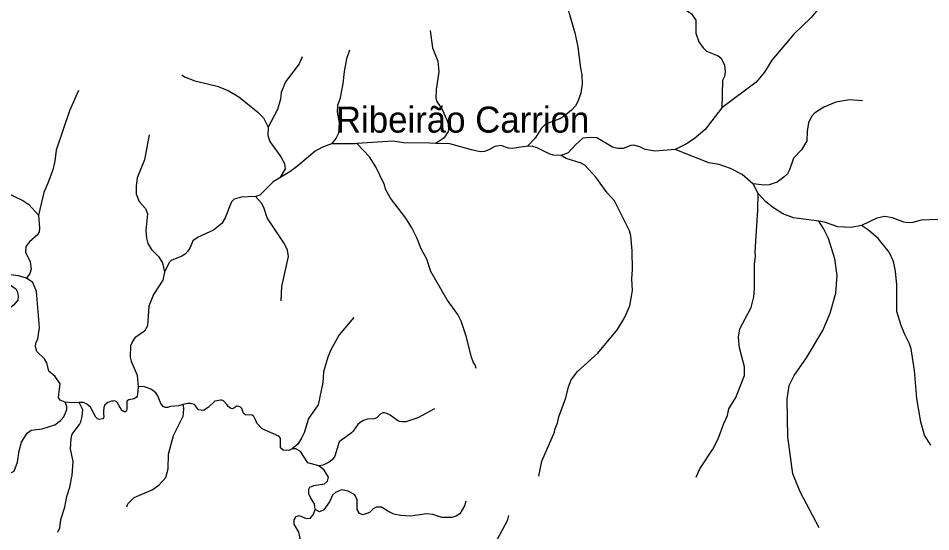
# Model space of a CAD drawing. Extents: x 500 to 555.2, y 9115.7 to 9171.
# Drawn here: x 511.43 to 518.44, y 9126.41 to 9130.35 of the extents above; entities that cross this region are included whole.
import ezdxf
from ezdxf.enums import TextEntityAlignment as Align

# ---------------------------------------------------------------- set-up
doc = ezdxf.new("R2010")
doc.units = 0
doc.header["$LTSCALE"] = 0.064
doc.layers.add('61', color=7, linetype='Continuous')
doc.layers.add('7', color=7, linetype='Continuous', lineweight=25)

msp = doc.modelspace()

# ---------------------------------------------------------------- linework, layer by layer
at = {"layer": '7'}
msp.add_line((512.5491, 9128.3991), (512.5369, 9128.3375), dxfattribs=at)
for points in [[(515.2472, 9130.9806), (515.3445, 9130.9612), (515.3856, 9130.9335), (515.4135, 9130.9056), (515.4543, 9130.8482), (515.4565, 9130.8327), (515.6452, 9130.44), (515.704, 9130.2374), (515.7268, 9130.1297), (515.7435, 9129.9839), (515.7581, 9129.9117), (515.7596, 9129.845), (515.7492, 9129.774), (515.7249, 9129.7092), (515.7071, 9129.6771), (515.678, 9129.6431), (515.6218, 9129.5967), (515.5872, 9129.5777), (515.4771, 9129.5371), (515.446, 9129.5058), (515.3982, 9129.4273), (515.3402, 9129.3668)], [(516.2338, 9130.6735), (516.2441, 9130.6339), (516.27, 9130.5794), (516.2861, 9130.5676), (516.3069, 9130.5407), (516.4113, 9130.4831), (516.5432, 9130.4204), (516.5986, 9130.3831), (516.6337, 9130.3346), (516.634, 9130.2335), (516.6572, 9130.1671), (516.6887, 9130.1225), (516.7156, 9130.0973), (516.8053, 9130.0601), (516.8241, 9130.0444), (516.8523, 9129.992), (516.8587, 9129.9383), (516.8521, 9129.9008), (516.8391, 9129.8706), (516.8338, 9129.6601)], [(517.5727, 9130.4215), (517.5725, 9130.42), (517.5159, 9130.3525), (517.3872, 9130.227), (517.2162, 9130.0264), (517.1615, 9129.9357), (517.0964, 9129.8592), (516.8338, 9129.6601)], [(511.3289, 9130.3305), (511.3189, 9130.3063), (511.3144, 9130.2586), (511.3374, 9130.074), (511.3341, 9130.0052), (511.3244, 9129.9466), (511.2703, 9129.799), (511.2587, 9129.7486), (511.2586, 9129.7042), (511.2819, 9129.5853), (511.3334, 9129.4822), (511.3373, 9129.4323), (511.3133, 9129.3694), (511.2704, 9129.2126), (511.267, 9129.128), (511.2717, 9129.0806), (511.2884, 9129.048), (511.3216, 9129.0169), (511.462, 9128.9504), (511.5059, 9128.918), (511.5809, 9128.8379)], [(514.591, 9130.2543), (514.6093, 9130.1219), (514.6505, 9130.0188), (514.6588, 9129.9368), (514.6377, 9129.8017), (514.6346, 9129.735), (514.6415, 9129.7089), (514.6852, 9129.6424), (514.718, 9129.5753), (514.7293, 9129.5399), (514.7321, 9129.4855), (514.6995, 9129.4309), (514.634, 9129.3885)], [(513.6066, 9130.0527), (513.5842, 9129.9998), (513.48, 9129.8612), (513.4454, 9129.7793), (513.44, 9129.729), (513.4172, 9129.6475), (513.3472, 9129.5126)], [(513.971, 9130.1042), (513.9493, 9130.0374), (513.9306, 9129.9415), (513.9192, 9129.8449), (513.896, 9129.729), (513.8799, 9129.6797), (513.8766, 9129.6299), (513.8929, 9129.5459), (513.888, 9129.4678), (513.8659, 9129.4256), (513.8338, 9129.3853)], [(512.6822, 9129.9144), (512.7042, 9129.9006), (512.783, 9129.8693), (512.9547, 9129.8279), (513.0399, 9129.795), (513.12, 9129.7446), (513.2681, 9129.6277), (513.3096, 9129.5841), (513.3472, 9129.5126)], [(511.8899, 9129.7954), (511.8186, 9129.6389), (511.7163, 9129.3352), (511.7078, 9129.2517), (511.6917, 9129.185), (511.6538, 9129.0827), (511.6211, 9129.0121), (511.5809, 9128.8379)], [(517.9129, 9129.716), (517.8138, 9129.7229), (517.7101, 9129.7054), (517.6179, 9129.6663), (517.5462, 9129.6202), (517.5246, 9129.5966), (517.4985, 9129.5492), (517.4885, 9129.4808), (517.4851, 9129.4073), (517.4463, 9129.3393), (517.383, 9129.2744), (517.3538, 9129.185), (517.3366, 9129.1545), (517.3102, 9129.1282), (517.2577, 9129.0903), (517.1959, 9129.0693), (517.1604, 9129.0669), (517.0714, 9129.0785)], [(516.8338, 9129.6601), (516.7048, 9129.4941), (516.6203, 9129.4221), (516.5623, 9129.3838), (516.4749, 9129.3408)], [(513.3472, 9129.5126), (513.3468, 9129.5119), (513.345, 9129.4489), (513.3594, 9129.4033), (513.4443, 9129.2854), (513.4715, 9129.2336), (513.4761, 9129.1932), (513.4361, 9129.1234)], [(512.433, 9129.4532), (512.397, 9129.2627), (512.3406, 9129.123), (512.3331, 9129.0603), (512.3331, 9129.0005), (512.3548, 9128.9415), (512.403, 9128.8885), (512.4198, 9128.8479), (512.4052, 9128.72), (512.4102, 9128.6607), (512.4213, 9128.6204), (512.4496, 9128.5731), (512.5028, 9128.52), (512.5345, 9128.4704), (512.5491, 9128.3991)], [(516.4749, 9129.3408), (516.3213, 9129.3293), (516.2434, 9129.3421), (516.2031, 9129.3617), (516.1534, 9129.3735), (516.1323, 9129.3714), (516.0745, 9129.3491), (516.0337, 9129.3493), (515.9931, 9129.3602), (515.871, 9129.4307), (515.8205, 9129.4341), (515.7656, 9129.4272), (515.7079, 9129.3775), (515.6508, 9129.3167), (515.5992, 9129.295)], [(513.8338, 9129.3853), (513.7585, 9129.3555), (513.7077, 9129.3276), (513.5736, 9129.2149), (513.5124, 9129.1702), (513.4361, 9129.1234)], [(514.0265, 9129.3865), (514.0151, 9129.3858), (513.8338, 9129.3853)], [(514.634, 9129.3885), (514.5888, 9129.3909), (514.3857, 9129.3933), (514.3063, 9129.4047), (514.0265, 9129.3865)], [(514.9448, 9127.66), (514.9375, 9127.6873), (514.9252, 9127.703), (514.9082, 9127.7455), (514.8689, 9127.9088), (514.8294, 9128.0234), (514.8029, 9128.0733), (514.7211, 9128.1882), (514.5966, 9128.4044), (514.5654, 9128.4991), (514.5221, 9128.5797), (514.4886, 9128.6628), (514.45, 9128.7399), (514.4031, 9128.8142), (514.2854, 9128.9687), (514.2476, 9129.0368), (514.2408, 9129.0695), (514.175, 9129.2079), (514.1245, 9129.2861), (514.0265, 9129.3865)], [(515.3402, 9129.3668), (515.2235, 9129.3491), (515.1939, 9129.3527), (515.1337, 9129.3716), (515.0888, 9129.3651), (515.0426, 9129.3382), (515.0091, 9129.3263), (514.9762, 9129.3244), (514.9085, 9129.338), (514.7434, 9129.3856), (514.634, 9129.3885)], [(515.5992, 9129.295), (515.5371, 9129.2985), (515.5052, 9129.3091), (515.4145, 9129.3541), (515.3808, 9129.3641), (515.3402, 9129.3668)], [(515.4257, 9126.8323), (515.4498, 9126.9475), (515.5473, 9127.172), (515.5483, 9127.1901), (515.5692, 9127.2397), (515.5792, 9127.2888), (515.6345, 9127.4352), (515.6547, 9127.5184), (515.6753, 9127.573), (515.7235, 9127.6364), (515.879, 9127.7772), (516.0302, 9127.9581), (516.086, 9128.0499), (516.1252, 9128.1412), (516.1451, 9128.2592), (516.1402, 9128.3479), (516.1452, 9128.4182), (516.1434, 9128.5622), (516.1332, 9128.6777), (516.1221, 9128.7157), (516.0081, 9128.946), (515.9528, 9129.0091), (515.8639, 9129.128), (515.7798, 9129.2206), (515.7524, 9129.2376), (515.6359, 9129.2732), (515.5992, 9129.295)], [(517.0714, 9129.0785), (516.9898, 9129.1503), (516.8999, 9129.1952), (516.8117, 9129.2253), (516.7326, 9129.2396), (516.4749, 9129.3408)], [(513.4361, 9129.1234), (513.3858, 9129.0926), (513.2834, 9128.9918), (513.2483, 9128.9793), (513.2482, 9128.9793)], [(517.1124, 9129.003), (517.0734, 9129.0767), (517.0714, 9129.0785)], [(516.6358, 9126.825), (516.6636, 9126.8885), (516.7647, 9127.039), (516.8052, 9127.1196), (516.8474, 9127.2369), (516.8759, 9127.3), (516.8874, 9127.3492), (516.9394, 9127.4376), (517.0082, 9127.605), (517.0079, 9127.6726), (516.9681, 9127.8189), (516.9604, 9127.9003), (516.9717, 9127.9641), (517.0576, 9128.1281), (517.0784, 9128.2112), (517.0848, 9128.275), (517.085, 9128.4579), (517.0914, 9128.5211), (517.0883, 9128.5557), (517.1096, 9128.8761), (517.1124, 9129.003)], [(517.5789, 9128.7903), (517.3829, 9128.8178), (517.3016, 9128.8471), (517.2217, 9128.8976), (517.1703, 9128.939), (517.1124, 9129.003)], [(513.2482, 9128.9793), (513.1378, 9128.9747), (513.0845, 9128.96), (513.0658, 9128.9397), (513.0161, 9128.8157), (512.9895, 9128.7738), (512.9252, 9128.7208), (512.8072, 9128.6681), (512.7684, 9128.6391), (512.7467, 9128.5897), (512.7296, 9128.5597), (512.7097, 9128.5384), (512.682, 9128.5232), (512.6004, 9128.4889), (512.5846, 9128.4728), (512.5491, 9128.3991)], [(513.4459, 9128.1804), (513.4517, 9128.2887), (513.5024, 9128.5185), (513.4943, 9128.5682), (513.473, 9128.6174), (513.3389, 9128.8159), (513.3123, 9128.8962), (513.2958, 9128.9291), (513.2482, 9128.9793)], [(511.5809, 9128.8379), (511.5898, 9128.7395), (511.5867, 9128.7068), (511.5759, 9128.6874), (511.5114, 9128.6321), (511.4835, 9128.597), (511.482, 9128.5535), (511.5162, 9128.4796), (511.5259, 9128.4232), (511.5157, 9128.3902), (511.4888, 9128.3522)], [(517.5813, 9126.4373), (517.4339, 9126.7122), (517.3782, 9126.8508), (517.3393, 9127.134), (517.3343, 9127.424), (517.3507, 9127.5281), (517.3881, 9127.6064), (517.4823, 9127.7404), (517.6089, 9127.9527), (517.6645, 9128.0841), (517.7079, 9128.2387), (517.7181, 9128.3728), (517.7018, 9128.502), (517.6525, 9128.6568), (517.6131, 9128.7356), (517.5789, 9128.7903)], [(517.907, 9128.7573), (517.8257, 9128.7426), (517.7233, 9128.7474), (517.622, 9128.7843), (517.5789, 9128.7903)], [(519.4267, 9128.5195), (519.342, 9128.5565), (519.2896, 9128.5617), (519.2385, 9128.557), (519.1923, 9128.5382), (519.1312, 9128.4871), (519.0658, 9128.4517), (519.037, 9128.4469), (519.008, 9128.4564), (518.9728, 9128.4901), (518.9149, 9128.6537), (518.8614, 9128.7027), (518.7883, 9128.7417), (518.7285, 9128.765), (518.6111, 9128.7895), (518.4917, 9128.8027), (518.3659, 9128.7996), (518.2995, 9128.7801), (518.266, 9128.7782), (518.2326, 9128.7834), (518.144, 9128.8176), (518.0862, 9128.8257), (518.0252, 9128.8153), (517.907, 9128.7573)], [(518.4386, 9127.0703), (518.3904, 9127.1484), (518.361, 9127.2501), (518.3316, 9127.4298), (518.3135, 9127.6431), (518.2891, 9127.8098), (518.2762, 9127.8493), (518.2391, 9127.9201), (518.2102, 9127.9909), (518.1775, 9128.0985), (518.1772, 9128.3032), (518.1676, 9128.4068), (518.1526, 9128.4803), (518.12, 9128.5518), (518.0333, 9128.6579), (517.9601, 9128.721), (517.907, 9128.7573)], [(511.4888, 9128.3522), (511.4285, 9128.3713), (511.3685, 9128.378), (511.3364, 9128.3696), (511.3294, 9128.3552), (511.3375, 9128.3211), (511.4066, 9128.2703), (511.4212, 9128.2455), (511.4262, 9128.2156), (511.4219, 9128.1853), (511.3901, 9128.1451), (511.367, 9128.1273), (511.3087, 9128.1034), (511.207, 9128.0844), (511.103, 9128.0286), (510.9846, 9128.0271)], [(511.6278, 9127.7348), (511.5693, 9127.7903), (511.5572, 9127.8268), (511.5601, 9127.8551), (511.5769, 9127.8865), (511.5899, 9127.9751), (511.5672, 9128.2518), (511.5373, 9128.3188), (511.4888, 9128.3522)], [(512.5369, 9128.3375), (512.4663, 9128.2276), (512.4285, 9128.139), (512.4179, 9127.9867), (512.3955, 9127.946), (512.3221, 9127.8945), (512.3036, 9127.8678), (512.2887, 9127.8327), (512.2857, 9127.7465), (512.2925, 9127.7164), (512.3394, 9127.6076), (512.3466, 9127.5173)], [(514.0037, 9128.0519), (513.893, 9127.9186), (513.8283, 9127.8026), (513.8054, 9127.7461), (513.7716, 9127.6332), (513.7666, 9127.5514), (513.7306, 9127.3795), (513.6562, 9127.2763), (513.622, 9127.1669), (513.6026, 9127.1235), (513.5734, 9127.0798), (513.5311, 9127.0433)], [(511.7852, 9127.4), (511.7473, 9127.4176), (511.7344, 9127.4361), (511.7466, 9127.5427), (511.7085, 9127.5983), (511.6611, 9127.6396), (511.6456, 9127.7021), (511.6278, 9127.7348)], [(512.3466, 9127.5173), (512.3424, 9127.4626), (512.3392, 9127.4481), (512.3307, 9127.4368), (512.3172, 9127.4275), (512.2761, 9127.419), (512.264, 9127.4105), (512.2595, 9127.4031), (512.2597, 9127.35), (512.2577, 9127.3348), (512.2534, 9127.329), (512.2464, 9127.3269), (512.2399, 9127.3276), (512.2314, 9127.3311), (512.2216, 9127.3376), (512.2088, 9127.3602), (512.2012, 9127.3736), (512.1875, 9127.3955), (512.1783, 9127.4056), (512.1662, 9127.4105), (512.155, 9127.4098), (512.1422, 9127.4098), (512.1131, 9127.3985), (512.0919, 9127.3797), (512.084, 9127.3609), (512.0805, 9127.3333), (512.0805, 9127.3085), (512.0825, 9127.2921), (512.0812, 9127.2801), (512.0758, 9127.2722), (512.0477, 9127.2677), (512.0337, 9127.2737), (512.0217, 9127.2855), (511.9802, 9127.3618), (511.9528, 9127.386), (511.9268, 9127.3987), (511.8949, 9127.3977)], [(512.6909, 9127.384), (512.6581, 9127.3733), (512.5967, 9127.3674), (512.5715, 9127.3596), (512.5557, 9127.3596), (512.5392, 9127.3684), (512.5209, 9127.3903), (512.4975, 9127.45), (512.4837, 9127.4729), (512.4508, 9127.4981), (512.4199, 9127.5119), (512.3954, 9127.5185), (512.365, 9127.5218), (512.3466, 9127.5173)], [(511.1845, 9126.7605), (511.1994, 9126.7897), (511.2441, 9126.8239), (511.3172, 9126.8458), (511.3544, 9126.8511), (511.3943, 9126.8704), (511.4194, 9126.9411), (511.4319, 9127.0267), (511.4516, 9127.0933), (511.4946, 9127.1635), (511.526, 9127.1854), (511.6103, 9127.1971), (511.7074, 9127.2271), (511.7496, 9127.2596), (511.7772, 9127.2893), (511.7993, 9127.3455), (511.7981, 9127.3679), (511.7852, 9127.4)], [(511.7301, 9126.4028), (511.744, 9126.4358), (511.754, 9126.5009), (511.7825, 9126.5954), (511.7996, 9126.6773), (511.8229, 9126.7476), (511.8393, 9126.8394), (511.8475, 9126.9464), (511.8263, 9127.0433), (511.8313, 9127.1221), (511.8398, 9127.1545), (511.8962, 9127.2284), (511.9075, 9127.2497), (511.9146, 9127.2808), (511.9203, 9127.3163), (511.9212, 9127.3422), (511.8949, 9127.3977)], [(511.8949, 9127.3977), (511.8351, 9127.3958), (511.7852, 9127.4)], [(513.5311, 9127.0433), (513.5058, 9127.0298), (513.4628, 9127.0318), (513.442, 9127.0501), (513.4402, 9127.1251), (513.4275, 9127.1406), (513.2993, 9127.1953), (513.2598, 9127.2389), (513.2546, 9127.2549), (513.2367, 9127.2902), (513.2308, 9127.2969), (513.2225, 9127.3003), (513.1724, 9127.305), (513.1637, 9127.3084), (513.159, 9127.3128), (513.1551, 9127.3216), (513.1438, 9127.3535), (513.1339, 9127.3616), (513.1211, 9127.3673), (513.108, 9127.3708), (513.1003, 9127.3707), (513.089, 9127.3609), (513.0822, 9127.3552), (513.072, 9127.3507), (513.0593, 9127.3533), (513.0394, 9127.3687), (513.0325, 9127.3797), (513.0025, 9127.4121), (512.991, 9127.4161), (512.9788, 9127.4165), (512.9352, 9127.4083), (512.8846, 9127.3614), (512.8506, 9127.3381), (512.8109, 9127.3413), (512.7799, 9127.383), (512.7458, 9127.3908), (512.7288, 9127.3914), (512.6909, 9127.384)], [(512.2591, 9126.5969), (512.2682, 9126.6204), (512.3161, 9126.6699), (512.4546, 9126.7289), (512.5053, 9126.7639), (512.5609, 9126.823), (512.5774, 9126.8891), (512.5809, 9127.0014), (512.6191, 9127.1456), (512.6923, 9127.2943), (512.6965, 9127.3136), (512.6972, 9127.355), (512.6954, 9127.3717), (512.6909, 9127.384)], [(514.6255, 9127.3492), (514.4968, 9127.2813), (514.4034, 9127.2514), (514.3758, 9127.2495), (514.3568, 9127.2538), (514.3393, 9127.2612), (514.2828, 9127.3005), (514.2578, 9127.3134), (514.2407, 9127.3184), (514.2287, 9127.3183), (514.208, 9127.3083), (514.1841, 9127.2836), (514.1729, 9127.2779), (514.1609, 9127.273), (514.1062, 9127.2706), (514.0794, 9127.2607), (514.0539, 9127.2462), (514.035, 9127.2291), (513.9989, 9127.1786), (513.986, 9127.1654), (513.8911, 9127.0978), (513.8587, 9126.9877), (513.8374, 9126.9593), (513.8151, 9126.9407), (513.7692, 9126.9186), (513.7352, 9126.913)], [(513.7352, 9126.913), (513.7351, 9126.9131), (513.6503, 9126.9363), (513.5945, 9127.0228), (513.5578, 9127.0431), (513.5311, 9127.0433)], [(513.707, 9126.578), (513.7024, 9126.6211), (513.6732, 9126.6639), (513.6588, 9126.6977), (513.6586, 9126.7342), (513.6673, 9126.7476), (513.6962, 9126.7605), (513.7787, 9126.7728), (513.8028, 9126.7941), (513.8091, 9126.826), (513.7765, 9126.88), (513.7352, 9126.913)], [(514.8649, 9126.6399), (514.8561, 9126.6058), (514.8202, 9126.5432), (514.7918, 9126.5261), (514.7578, 9126.516), (514.6815, 9126.5163), (514.6114, 9126.539), (514.5628, 9126.544), (514.4435, 9126.5261), (514.366, 9126.5309), (514.3132, 9126.5419), (514.2658, 9126.5644), (514.2185, 9126.5949), (514.177, 9126.5959), (514.1543, 9126.5821), (514.1251, 9126.554), (514.0755, 9126.5361), (514.0487, 9126.5465), (514.0312, 9126.5764), (514.0293, 9126.6522), (514.0125, 9126.6899), (513.9614, 9126.718), (513.9094, 9126.7292), (513.8641, 9126.7067), (513.8416, 9126.6878), (513.8182, 9126.637), (513.7742, 9126.575), (513.7414, 9126.5593), (513.707, 9126.578)], [(513.5153, 9126.1907), (513.524, 9126.2197), (513.5567, 9126.2587), (513.5731, 9126.2883), (513.5911, 9126.3571), (513.5813, 9126.403), (513.5472, 9126.4633), (513.5455, 9126.498), (513.5603, 9126.5225), (513.5851, 9126.5309), (513.639, 9126.5082), (513.6725, 9126.511), (513.6954, 9126.5417), (513.707, 9126.578)], [(515.1921, 9126.532), (515.1839, 9126.4888), (515.105, 9126.3473)]]:
    msp.add_lwpolyline(points, dxfattribs=at)

# ---------------------------------------------------------------- texts
at = {"layer": '61'}
msp.add_text('Ribeirão Carrion', height=0.2, dxfattribs=at).set_placement((514.8406, 9129.4709), align=Align.CENTER)

doc.saveas('drawing.dxf')
